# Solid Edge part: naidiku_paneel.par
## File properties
Author: Mac
Template: Normal.par
Last saved by: Mac
Revision: 3
Application: Solid Edge
Material: Wood, Mahogany
Face Style: Tan
Fill Style: Cork
Virtual Style: Polished mahogany
Coef. of Thermal Exp: 0.0
Thermal Conductivity: 0.0
Specific Heat: 0.0
Modulus of Elasticity: 0.0
Poission's Ratio: 0.0
Yield Stress: 0.0
Ultimate Stress: 0.0
Elongation: 0.0
Density: 600,000 kg/m^3
Accuracy: 0,990
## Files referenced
..\Asm16.asm
5C:\Documents and Settings\Mac\Desktop\paat5\Asm16.asm
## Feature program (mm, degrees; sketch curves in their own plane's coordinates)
sketch for "unnamed Protrusion 1" plane through (0.2496, -21.0021, 0.7916) normal (-0.953717, 0, 0.300706) x-axis (0, -1, 0)
extrude "unnamed Protrusion 1" add finite 0.03 along -normal
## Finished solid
Body 1: solid body, 8 faces, 18 edges, 12 vertices.
  Faces by surface: plane 6, cylinder 2
  Edges by curve: line 14, circle 4
Bounding box of the edges (mm): 0.528 x 14.205 x 1.592, from (0, -28.1045, -0.009) to (0.5278, -13.8996, 1.5831).
Cylindrical faces by radius (mm): R1.3 x2
Planar faces by outward normal: +y 1, -y 1, oblique 4
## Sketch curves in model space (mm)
line (0, -13.8996, 0) -> (0, -28.1045, 0)
line (0, -28.1045, 0) -> (0.1082, -28.1045, 0.3433)
arc centre (0.1082, -26.8045, 0.3433) radius 1.3 from (0.1082, -28.1045, 0.3433) through (0.3926, -27.6966, 1.2451) to (0.4992, -26.8045, 1.5831)
line (0.4992, -26.8045, 1.5831) -> (0.4992, -15.1996, 1.5831)
arc centre (0.1082, -15.1996, 0.3433) radius 1.3 from (0.4992, -15.1996, 1.5831) through (0.3765, -14.254, 1.1941) to (0.1082, -13.8996, 0.3433)
line (0.1082, -13.8996, 0.3433) -> (0, -13.8996, 0)
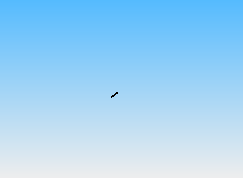
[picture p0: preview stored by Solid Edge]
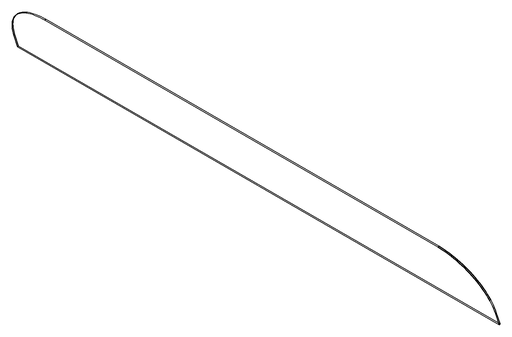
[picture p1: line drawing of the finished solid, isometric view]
